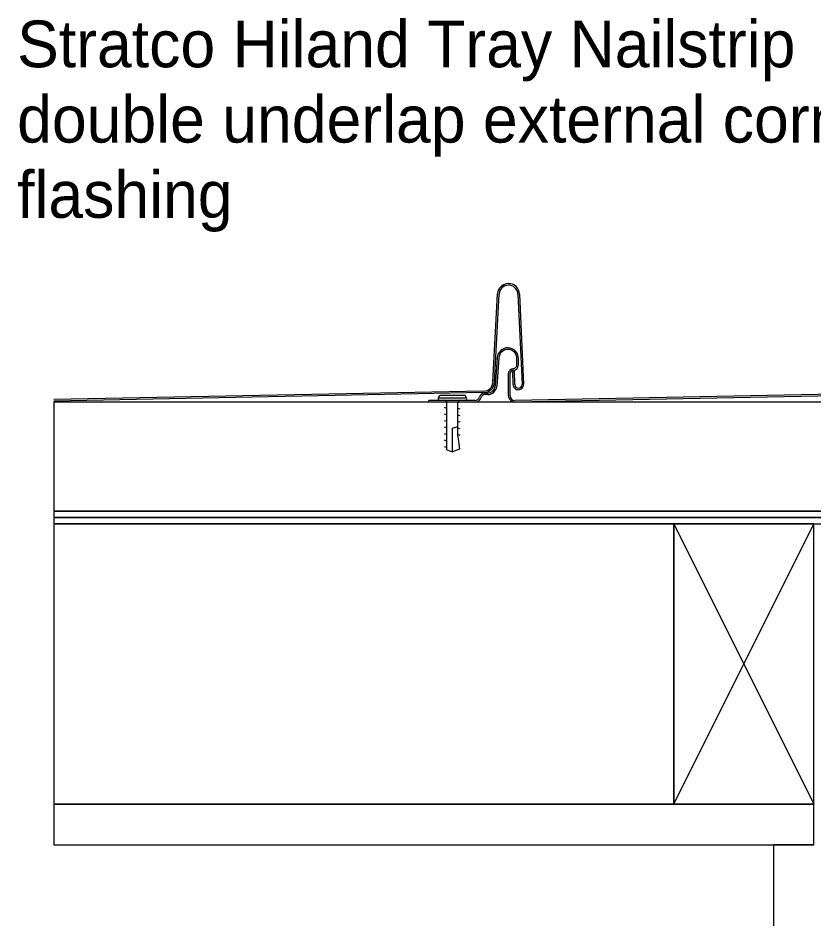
# Model space of a CAD drawing. Extents: x -2.36 to 6.66, y -3.72 to 4.13.
# Drawn here: x 1.223 to 1.4784, y -2.1658 to -1.8768 of the extents above; entities that cross this region are included whole.
import ezdxf

# ---------------------------------------------------------------- set-up
doc = ezdxf.new("R2010")
doc.units = 0
for name, color, linetype in [('A-____-____-IDEN', 7, 'Continuous'), ('A-DETL-____-MEDM', 7, 'Continuous'), ('A-DETL-GENF-OTLN', 7, 'Continuous'), ('A-WALL-____-MCUT', 7, 'Continuous'), ('A-WALL-____-PATT', 7, 'Continuous'), ('A-WALL-FNSH-MCUT', 7, 'Continuous')]:
    doc.layers.add(name, color=color, linetype=linetype)

# ---------------------------------------------------------------- blocks, each defined once
blk = doc.blocks.new('Detail Repeating_Stratco_Hiland_Tray_Nailstrip - Rib Height 38mm_165mm Coverage-V16-Detail Flashings - Hiland Nailstrip Corner')
at = {"layer": 'A-DETL-____-MEDM'}
for p, q in [((0.17571069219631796, 7.14861503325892e-16), (0.1905651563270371, 7.14861503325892e-16)), ((0.1905651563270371, 7.14861503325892e-16), (0.1905651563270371, -0.0004999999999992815)), ((0.008000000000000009, -0.0035284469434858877), (0.16297544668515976, -0.0005002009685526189)), ((0.00800101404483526, -0.0030284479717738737), (0.16296726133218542, -2.6797304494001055e-07)), ((0.1644999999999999, -0.002), (0.1644999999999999, -0.009238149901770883)), ((0.1649999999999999, -0.002), (0.1649999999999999, -0.009238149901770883)), ((0.17162103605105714, -0.002413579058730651), (0.17257033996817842, -0.002413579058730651)), ((0.1730000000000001, -0.0035284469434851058), (0.31092747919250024, -0.000833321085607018)), ((0.1730010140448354, -0.0030284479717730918), (0.31092747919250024, -0.00033324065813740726)), ((0.17571069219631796, -0.0004999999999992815), (0.1905651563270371, -0.0004999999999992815)), ((-0.0035190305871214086, -0.03458502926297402), (-0.00482759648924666, -0.005699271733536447)), ((-0.0030193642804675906, -0.03456634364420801), (-0.004327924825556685, -0.005680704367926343)), ((-0.001993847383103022, -0.005613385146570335), (-0.001867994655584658, -0.009787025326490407)), ((-0.0014940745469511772, -0.005598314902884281), (-0.0013682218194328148, -0.009771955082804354)), ((0.16148096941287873, -0.03458502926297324), (0.16017240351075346, -0.005699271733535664)), ((0.16198063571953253, -0.03456634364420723), (0.16067207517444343, -0.00568070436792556)), ((0.1630061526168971, -0.005613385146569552), (0.16313200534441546, -0.009787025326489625)), ((0.16350592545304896, -0.005598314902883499), (0.16363177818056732, -0.009771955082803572)), ((0.16813551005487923, -0.014184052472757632), (0.16879587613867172, -0.00504202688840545)), ((0.1686342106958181, -0.014220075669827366), (0.16929457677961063, -0.005078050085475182)), ((0.17162103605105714, -0.002913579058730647), (0.17257033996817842, -0.002913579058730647)), ((0.0044987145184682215, -0.006345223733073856), (0.003015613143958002, -0.034638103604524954)), ((0.004998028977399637, -0.006371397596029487), (0.00351492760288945, -0.03466427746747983)), ((0.16949871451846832, -0.006345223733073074), (0.1680156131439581, -0.03463810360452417)), ((0.16999802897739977, -0.006371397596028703), (0.16851492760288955, -0.034664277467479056)), ((-0.0013682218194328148, -0.009771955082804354), (-0.001867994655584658, -0.009787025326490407)), ((0.16363177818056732, -0.009771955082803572), (0.16313200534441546, -0.009787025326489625)), ((0.16179429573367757, -0.012056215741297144), (0.16179429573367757, -0.013973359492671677)), ((0.16229429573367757, -0.012056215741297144), (0.16229429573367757, -0.013973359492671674))]:
    blk.add_line(p, q, dxfattribs=at)
for centre, radius, start, end in [((0.1629999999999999, -0.002), 0.0020000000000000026, 359.9999999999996, 90.00000000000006), ((0.17571069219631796, -0.0019038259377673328), 0.0019038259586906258, 90, 165.0895671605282), ((0.1629999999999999, -0.002), 0.0015000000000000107, 359.99999999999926, 89.99999999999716), ((0.17162103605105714, -0.005246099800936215), 0.002832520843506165, 90, 175.86846616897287), ((0.17257033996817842, -0.0010676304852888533), 0.0013459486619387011, 269.9999999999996, 345.0895671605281), ((0.17257033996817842, -0.0010676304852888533), 0.0018459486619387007, 269.9999999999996, 345.08956716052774), ((0.17571069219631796, -0.0019038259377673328), 0.0014038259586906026, 90, 165.0895671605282), ((-0.0031614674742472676, -0.00564870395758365), 0.0016668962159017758, 91.69561024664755, 181.73841940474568), ((-0.0031614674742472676, -0.00564870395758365), 0.0011668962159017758, 91.68553350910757, 181.57144938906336), ((-0.003160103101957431, -0.005648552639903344), 0.0016667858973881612, 1.7271842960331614, 91.74264393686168), ((-0.003160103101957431, -0.005648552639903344), 0.0011667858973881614, 1.727184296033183, 91.75272148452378), ((0.007993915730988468, -0.006528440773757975), 0.003499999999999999, 89.88379894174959, 176.9993247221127), ((0.007993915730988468, -0.006528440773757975), 0.0029999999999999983, 89.88379894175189, 173.99932472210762), ((0.16183853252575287, -0.005648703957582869), 0.001666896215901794, 91.69561024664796, 181.73841940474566), ((0.16183853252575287, -0.005648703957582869), 0.0011668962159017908, 91.68553350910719, 181.57144938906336), ((0.16183989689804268, -0.005648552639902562), 0.0016667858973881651, 1.727184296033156, 91.74264393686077), ((0.16183989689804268, -0.005648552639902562), 0.0011667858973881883, 1.7271842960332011, 91.75272148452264), ((0.17162103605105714, -0.005246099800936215), 0.0023325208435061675, 90, 175.8684661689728), ((0.1729939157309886, -0.006528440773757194), 0.0035000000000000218, 89.88379894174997, 176.99932472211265), ((0.1729939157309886, -0.006528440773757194), 0.0029999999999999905, 89.88379894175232, 173.99932472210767), ((0.16369429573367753, -0.012056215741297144), 0.0019000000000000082, 97.16745519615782, 180), ((0.16369429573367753, -0.012056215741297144), 0.0014000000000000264, 99.1545104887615, 180), ((0.1635613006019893, -0.009238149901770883), 0.0009386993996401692, 263.63492002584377, 0), ((0.1635613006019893, -0.009238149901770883), 0.001438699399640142, 266.42375988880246, 0), ((0.1652187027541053, -0.013973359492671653), 0.0034244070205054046, 180.0000000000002, 355.8684661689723), ((0.1652187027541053, -0.013973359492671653), 0.0029244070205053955, 180.0000000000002, 355.8684661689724), ((-3.378274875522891e-07, -0.034479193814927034), 0.003520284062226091, 181.72282641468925, 271.7282292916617), ((-3.378274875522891e-07, -0.034479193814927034), 0.003020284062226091, 181.65349035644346, 271.7291069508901), ((3.394205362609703e-07, -0.03448004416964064), 0.0030194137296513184, 271.71674837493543, 356.9993247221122), ((3.394205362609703e-07, -0.03448004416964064), 0.003519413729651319, 271.7176262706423, 356.9993247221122), ((0.16499966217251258, -0.03447919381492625), 0.0035202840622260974, 181.72282641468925, 271.72822929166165), ((0.16499966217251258, -0.03447919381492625), 0.0030202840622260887, 181.65349035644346, 271.72910695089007), ((0.16500033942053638, -0.03448004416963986), 0.00301941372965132, 271.71674837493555, 356.9993247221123), ((0.16500033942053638, -0.03448004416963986), 0.0035194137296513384, 271.7176262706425, 356.9993247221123)]:
    blk.add_arc(centre, radius, start, end, dxfattribs=at)
at = {"layer": 'A-DETL-GENF-OTLN'}
for p, q in [((0.18067801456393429, 0.015091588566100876), (0.1829999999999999, 0.015936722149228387)), ((0.18124999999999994, 0.011021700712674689), (0.18067801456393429, 0.015091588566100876)), ((0.18299999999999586, 0.015936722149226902), (0.18299999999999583, 0.008320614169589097)), ((0.18474999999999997, 0.015299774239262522), (0.1829999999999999, 0.015936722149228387)), ((0.18474999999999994, 0.015299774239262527), (0.1847499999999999, 0.000223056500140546)), ((0.18474999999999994, 0.014598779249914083), (0.18549999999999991, 0.014360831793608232)), ((0.18474999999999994, 0.012500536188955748), (0.18549999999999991, 0.012262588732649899)), ((0.18049999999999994, 0.01067627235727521), (0.18124999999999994, 0.010438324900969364)), ((0.18124999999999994, 0.011021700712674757), (0.1812499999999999, 0.00022305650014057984)), ((0.18474999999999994, 0.010402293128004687), (0.18549999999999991, 0.010164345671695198)), ((0.18049999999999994, 0.008578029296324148), (0.18124999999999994, 0.008340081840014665)), ((0.18049999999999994, 0.006479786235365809), (0.18124999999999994, 0.006241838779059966)), ((0.18299999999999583, 0.008320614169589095), (0.18124999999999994, 0.00781847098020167)), ((0.18474999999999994, 0.00830405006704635), (0.18549999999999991, 0.0080661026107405)), ((0.18474999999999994, 0.006205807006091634), (0.18549999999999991, 0.005967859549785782)), ((0.18049999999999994, 0.004381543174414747), (0.18124999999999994, 0.004143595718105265)), ((0.18474999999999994, 0.004107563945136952), (0.18549999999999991, 0.0038696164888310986)), ((0.1804999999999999, 0.002283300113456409), (0.1812499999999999, 0.002045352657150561)), ((0.1847499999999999, 0.00200932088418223), (0.1854999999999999, 0.0017713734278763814)), ((0.17899470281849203, -0.0022175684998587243), (0.17844206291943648, -0.001277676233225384)), ((0.17844780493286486, -0.0012874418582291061), (0.18755219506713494, -0.0012874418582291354)), ((0.1870999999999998, -0.0005769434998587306), (0.1789, -0.0005769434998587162)), ((0.1870052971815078, -0.0022175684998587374), (0.17899470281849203, -0.002217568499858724)), ((0.18755219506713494, -0.001287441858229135), (0.1870052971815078, -0.002217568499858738))]:
    blk.add_line(p, q, dxfattribs=at)
for centre, radius, start, end in [((0.18045000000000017, 0.00022305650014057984), 0.0007999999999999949, 269.99999999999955, 359.99999999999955), ((0.18554999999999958, 0.000223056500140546), 0.0007999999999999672, 179.99999999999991, 269.9999999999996), ((0.1789, -0.0010769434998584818), 0.0005000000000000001, 90.00000000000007, 203.66982389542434), ((0.18709999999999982, -0.0010769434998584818), 0.0004999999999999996, 336.3301761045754, 89.99999999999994)]:
    blk.add_arc(centre, radius, start, end, dxfattribs=at)
blk = doc.blocks.new('DET_ST_Framing Detail Timber - 45x90-V12-Detail Flashings - Hiland Nailstrip Corner')
at = {"layer": 'A-DETL-____-MEDM'}
for p, q in [((0.09000000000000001, 0.045000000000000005), (0, 0.045000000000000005)), ((0, 0.045000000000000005), (0, 0)), ((0.09000000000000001, 0), (0.09000000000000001, 0.045000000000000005)), ((0, 0), (0.09000000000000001, 0))]:
    blk.add_line(p, q, dxfattribs=at)
at = {"layer": 'A-DETL-GENF-OTLN'}
for p, q in [((0, 0.04500000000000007), (0.09000000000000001, 0)), ((0.09000000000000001, 0.045000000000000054), (0, 0))]:
    blk.add_line(p, q, dxfattribs=at)

msp = doc.modelspace()

# ---------------------------------------------------------------- linework, layer by layer
at = {"layer": 'A-WALL-____-MCUT'}
for p, q in [((1.5105326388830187, -2.000000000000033), (1.2344801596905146, -2.0000000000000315)), ((1.5105326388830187, -2.0350000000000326), (1.2344801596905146, -2.0350000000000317)), ((1.5704076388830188, -2.037000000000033), (1.2344801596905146, -2.0370000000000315)), ((1.4334076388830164, -2.039000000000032), (1.2344801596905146, -2.0390000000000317)), ((1.4334076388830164, -2.129000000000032), (1.2344801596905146, -2.1290000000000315))]:
    msp.add_line(p, q, dxfattribs=at)
at = {"layer": 'A-WALL-____-PATT'}
for p, q in [((1.5105326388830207, -2.000000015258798), (1.2344801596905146, -2.000000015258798)), ((1.2344801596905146, -2.000000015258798), (1.2344801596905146, -2.0350000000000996)), ((1.2344801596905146, -2.0350000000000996), (1.5105326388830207, -2.0350000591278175)), ((1.572408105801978, -2.0350000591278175), (1.2344801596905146, -2.0350000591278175)), ((1.2344801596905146, -2.0350000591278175), (1.2344801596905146, -2.036999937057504)), ((1.2344801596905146, -2.036999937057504), (1.5704070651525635, -2.036999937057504)), ((1.5704070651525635, -2.036999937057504), (1.2344801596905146, -2.036999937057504)), ((1.2344801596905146, -2.036999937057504), (1.2344801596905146, -2.0389999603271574)), ((1.2344801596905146, -2.0389999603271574), (1.5684071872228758, -2.0389999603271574)), ((1.4334076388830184, -2.0390000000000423), (1.2344801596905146, -2.0390000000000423)), ((1.2344801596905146, -2.0390000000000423), (1.2344801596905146, -2.128999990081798)), ((1.4334076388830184, -2.128999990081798), (1.4334076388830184, -2.0390000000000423)), ((1.2344801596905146, -2.128999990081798), (1.4334076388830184, -2.128999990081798)), ((1.4784074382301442, -2.129000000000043), (1.2344801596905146, -2.129000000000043)), ((1.2344801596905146, -2.129000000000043), (1.2344801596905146, -2.1420000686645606)), ((1.4784074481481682, -2.1420000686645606), (1.4784074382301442, -2.129000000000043)), ((1.2344801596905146, -2.1420000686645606), (1.4784074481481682, -2.1420000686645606)), ((1.47840763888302, -2.142000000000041), (1.4654076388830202, -2.142000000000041)), ((1.4654076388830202, -2.142000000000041), (1.4654076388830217, -2.7000000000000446))]:
    msp.add_line(p, q, dxfattribs=at)
at = {"layer": 'A-WALL-FNSH-MCUT'}
for p, q in [((1.2344801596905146, -2.1420000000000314), (1.4654076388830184, -2.142000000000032)), ((1.4654076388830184, -2.142000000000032), (1.4654076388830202, -2.7000000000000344))]:
    msp.add_line(p, q, dxfattribs=at)

# ---------------------------------------------------------------- block references
at = {"layer": 'A-DETL-GENF-OTLN'}
for name, p, rotation in [('Detail Repeating_Stratco_Hiland_Tray_Nailstrip - Rib Height 38mm_165mm Coverage-V16-Detail Flashings - Hiland Nailstrip Corner', (1.545407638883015, -2.000000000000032), 180), ('DET_ST_Framing Detail Timber - 45x90-V12-Detail Flashings - Hiland Nailstrip Corner', (1.4784076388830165, -2.1290000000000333), 89.9999999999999)]:
    msp.add_blockref(name, p, dxfattribs=dict(at, rotation=rotation))

# ---------------------------------------------------------------- texts
at = {"layer": 'A-____-____-IDEN'}
for s, p in [('Stratco Hiland Tray Nailstrip', (1.2227513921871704, -1.8926269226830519)), ('double underlap external corner', (1.2227513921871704, -1.9167701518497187)), ('flashing', (1.2227513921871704, -1.940913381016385))]:
    msp.add_text(s, height=0.014999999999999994, dxfattribs=at).set_placement(p)

doc.saveas('drawing.dxf')
